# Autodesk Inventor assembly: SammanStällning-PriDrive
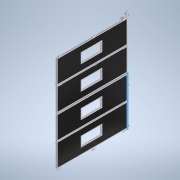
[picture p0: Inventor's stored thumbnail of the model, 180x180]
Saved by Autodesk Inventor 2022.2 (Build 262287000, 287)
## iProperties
Created: 2022-02
Part Number: SammanStällning-PriDrive
Document SubType Name: Assembly
Designer: cl
Author: cl
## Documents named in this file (17)
- G:\AutoCad\Carl Lund\3D-modeller systemlösningar\3D-modell-systemlösning-2022\SammanStällning-PriDrive.iam
- G:\AutoCad\Carl Lund\3D-modeller systemlösningar\3D-modell-systemlösning-2022\Parts\BladKomplett2022.iam
- G:\AutoCad\Carl Lund\3D-modeller systemlösningar\3D-modell-systemlösning-2022\Parts\MellanGångjärnH.ipt
- G:\AutoCad\Carl Lund\3D-modeller systemlösningar\3D-modell-systemlösning-2022\Parts\MellanGångjärnV.ipt
- G:\AutoCad\Carl Lund\3D-modeller systemlösningar\3D-modell-systemlösning-2022\Parts\Karmstyrning.ipt
- G:\AutoCad\Carl Lund\3D-modeller systemlösningar\3D-modell-systemlösning-2022\Parts\SidotätningUppe.ipt
- G:\AutoCad\Carl Lund\3D-modeller systemlösningar\3D-modell-systemlösning-2022\Parts\SidoTätning.ipt
- G:\AutoCad\Carl Lund\3D-modeller systemlösningar\3D-modell-systemlösning-2022\Parts\SläpList.ipt
- G:\AutoCad\Carl Lund\3D-modeller systemlösningar\3D-modell-systemlösning-2022\Parts\GummilistMellan.ipt
- G:\AutoCad\Carl Lund\3D-modeller systemlösningar\3D-modell-systemlösning-2022\Styrande.iam
- G:\AutoCad\Carl Lund\3D-modeller systemlösningar\3D-modell-systemlösning-2022\Parts\GarageregelHöger.ipt
- G:\AutoCad\Carl Lund\3D-modeller systemlösningar\3D-modell-systemlösning-2022\Parts\GarageregelVänster.ipt
- G:\AutoCad\Carl Lund\3D-modeller systemlösningar\3D-modell-systemlösning-2022\Parts\styrrulle.ipt
- G:\AutoCad\Carl Lund\3D-modeller systemlösningar\3D-modell-systemlösning-2022\Parts\Styrskena.ipt
- G:\AutoCad\Carl Lund\3D-modeller systemlösningar\3D-modell-systemlösning-2022\Parts\PriDrive\Karmgångjärn-PriDrive.ipt
- G:\AutoCad\Carl Lund\3D-modeller systemlösningar\3D-modell-systemlösning-2022\Parts\PriDrive\VinkeljärnStyrskena2.ipt
- G:\AutoCad\Carl Lund\3D-modeller systemlösningar\3D-modell-systemlösning-2022\Parts\PriDrive\VinkeljärnStyrskena.ipt
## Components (43 placed, 15 different names)
1. Karmgångjärn-PriDrive:1 — Mate:177, Flush:176, Mate:178, Flush:177, Flush:179, Flush:180
2. VinkeljärnStyrskena2:1 — Flush:179, Flush:180, Mate:181
3. VinkeljärnStyrskena2:2 — Flush:177, Flush:178, Mate:180, Flush:181, Flush:182
4. VinkeljärnStyrskena:1 — Mate:182, Flush:181, Flush:182
5. BladKomplett2022:1 [sub-assembly] — Mate:1, Mate:2, Flush:1, Flush:2, Flush:3, Flush:8, Flush:28, Flush:29, Mate:28, Flush:30, Mate:42, Mate:39, Mate:43, Flush:99, Flush:100, Flush:101, Flush:102, Flush:103, Flush:104, Flush:112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
6. BladKomplett2022:2 [sub-assembly] — Flush:2, Flush:3, Flush:8, Flush:106, Mate:52, Flush:107, Flush:118, Flush:121, Mate:65, Flush:148, Flush:149, Mate:82, Flush:170, Flush:171
7. BladKomplett2022:3 [sub-assembly] — Flush:30, Flush:101, Flush:102, Mate:53, Flush:114, Flush:115
8. BladKomplett2022:4 [sub-assembly] — Flush:32, Flush:100, Flush:103, Mate:54, Flush:122, Flush:123, Flush:128, Mate:64, Flush:146, Flush:147, Flush:178
9. BladKomplett2022:5 [sub-assembly] — Flush:31, Flush:99, Flush:104, Flush:129, Mate:55, Flush:130, Mate:63, Flush:144, Flush:145, Mate:81, Flush:168, Flush:169
10. BladKomplett2022:6 [sub-assembly] — Mate:28, Flush:28, Flush:29, Flush:31, Flush:32, Mate:38, Flush:131, Flush:134, Flush:137, Mate:56, Flush:138, Flush:139, Mate:58, Mate:59, Mate:62, Flush:142, Flush:143, Flush:152, Mate:69, Mate:70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
11. GarageregelHöger:1 — Flush:156, Flush:157, Flush:158
12. GarageregelHöger:2 — Mate:77, Flush:154, Flush:155, Flush:156, Flush:157, Flush:158
13. GarageregelVänster:1 — Flush:161, Flush:162, Flush:163
14. GarageregelVänster:2 — Mate:78, Flush:159, Flush:160, Flush:161, Flush:162, Flush:163
15. Karmstyrning:2 — Mate:38, Mate:56, Flush:138, Flush:141
16. Karmstyrning:3 — Mate:39, Mate:43, Flush:140
17. Karmstyrning:4 — Mate:42, Mate:60, Mate:61, Flush:141
18. Karmstyrning:1 — Flush:139, Mate:58, Mate:59, Flush:140
19. MellanGångjärnV:3 — Flush:110, Flush:111, Flush:113
20. MellanGångjärnV:2 — Flush:108, Flush:109, Flush:110, Flush:111, Flush:112
21. MellanGångjärnV:1 — Flush:106, Mate:52, Flush:107, Flush:108, Flush:109
22. MellanGångjärnH:2 — Flush:116, Flush:117, Flush:118, Flush:119, Flush:120
23. MellanGångjärnH:3 — Flush:119, Flush:120, Flush:121
24. MellanGångjärnH:1 — Mate:53, Flush:114, Flush:115, Flush:116, Flush:117
25. MellanGångjärnV:6 — Flush:124, Flush:125, Flush:126, Flush:127, Flush:128
26. MellanGångjärnV:5 — Flush:126, Flush:127, Flush:129
27. MellanGångjärnV:4 — Mate:54, Flush:122, Flush:123, Flush:124, Flush:125
28. MellanGångjärnH:5 — Flush:132, Flush:133, Flush:134
29. MellanGångjärnH:6 — Flush:135, Flush:136, Flush:137
30. MellanGångjärnH:4 — Mate:55, Flush:130, Flush:131, Flush:132, Flush:133, Flush:135, Flush:136
31. GummilistMellan:2 — Mate:63, Flush:144, Flush:145
32. GummilistMellan:3 — Mate:64, Flush:146, Flush:147
33. GummilistMellan:4 — Mate:65, Flush:148, Flush:149
34. GummilistMellan:5 — Mate:66, Flush:150, Flush:151
35. SidotätningUppe:1 — Mate:67, Mate:68, Flush:152, Mate:71, Mate:74
36. SidoTätning:1 — Mate:69, Mate:70, Mate:71, Mate:76
37. SidoTätning:2 — Mate:72, Mate:73, Mate:74
38. SläpList:1 — Mate:75, Flush:153, Mate:76
39. GummilistMellan:1 — Mate:62, Flush:142, Flush:143
40. styrrulle:1 — Mate:81, Flush:168, Flush:169
41. styrrulle:2 — Mate:82, Flush:170, Flush:171, Tangent:1
42. Styrskena:1 — Tangent:1, Flush:174, Flush:175, Mate:181
43. Styrskena:2 — Flush:174, Flush:175, Mate:179, Mate:180, Mate:182
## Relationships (128: Flush 86, Mate 41, Tangent 1)
- Mate:1: BladKomplett2022:1
- Mate:2: BladKomplett2022:1
- Flush:1: BladKomplett2022:1
- Flush:2: BladKomplett2022:1 ↔ BladKomplett2022:2
- Flush:3: BladKomplett2022:1 ↔ BladKomplett2022:2
- Flush:8: BladKomplett2022:1 ↔ BladKomplett2022:2
- Mate:28: BladKomplett2022:1 ↔ BladKomplett2022:6
- Flush:28: BladKomplett2022:1 ↔ BladKomplett2022:6
- Flush:29: BladKomplett2022:1 ↔ BladKomplett2022:6
- Flush:30: BladKomplett2022:1 ↔ BladKomplett2022:3
- Flush:31: BladKomplett2022:5 ↔ BladKomplett2022:6
- Flush:32: BladKomplett2022:4 ↔ BladKomplett2022:6
- Mate:38: BladKomplett2022:6 ↔ Karmstyrning:2
- Mate:39: BladKomplett2022:1 ↔ Karmstyrning:3
- Mate:42: BladKomplett2022:1 ↔ Karmstyrning:4
- Mate:43: BladKomplett2022:1 ↔ Karmstyrning:3
- Flush:99: BladKomplett2022:1 ↔ BladKomplett2022:5
- Flush:100: BladKomplett2022:1 ↔ BladKomplett2022:4
- Flush:101: BladKomplett2022:1 ↔ BladKomplett2022:3
- Flush:102: BladKomplett2022:1 ↔ BladKomplett2022:3
- Flush:103: BladKomplett2022:1 ↔ BladKomplett2022:4
- Flush:104: BladKomplett2022:1 ↔ BladKomplett2022:5
- Flush:106: BladKomplett2022:2 ↔ MellanGångjärnV:1
- Mate:52: BladKomplett2022:2 ↔ MellanGångjärnV:1
- Flush:107: BladKomplett2022:2 ↔ MellanGångjärnV:1
- Flush:108: MellanGångjärnV:2 ↔ MellanGångjärnV:1
- Flush:109: MellanGångjärnV:2 ↔ MellanGångjärnV:1
- Flush:110: MellanGångjärnV:3 ↔ MellanGångjärnV:2
- Flush:111: MellanGångjärnV:3 ↔ MellanGångjärnV:2
- Flush:112: BladKomplett2022:1 ↔ MellanGångjärnV:2
- Flush:113: BladKomplett2022:1 ↔ MellanGångjärnV:3
- Mate:53: BladKomplett2022:3 ↔ MellanGångjärnH:1
- Flush:114: BladKomplett2022:3 ↔ MellanGångjärnH:1
- Flush:115: BladKomplett2022:3 ↔ MellanGångjärnH:1
- Flush:116: MellanGångjärnH:2 ↔ MellanGångjärnH:1
- Flush:117: MellanGångjärnH:2 ↔ MellanGångjärnH:1
- Flush:118: BladKomplett2022:2 ↔ MellanGångjärnH:2
- Flush:119: MellanGångjärnH:2 ↔ MellanGångjärnH:3
- Flush:120: MellanGångjärnH:2 ↔ MellanGångjärnH:3
- Flush:121: BladKomplett2022:2 ↔ MellanGångjärnH:3
- Mate:54: BladKomplett2022:4 ↔ MellanGångjärnV:4
- Flush:122: BladKomplett2022:4 ↔ MellanGångjärnV:4
- Flush:123: BladKomplett2022:4 ↔ MellanGångjärnV:4
- Flush:124: MellanGångjärnV:6 ↔ MellanGångjärnV:4
- Flush:125: MellanGångjärnV:6 ↔ MellanGångjärnV:4
- Flush:126: MellanGångjärnV:6 ↔ MellanGångjärnV:5
- Flush:127: MellanGångjärnV:6 ↔ MellanGångjärnV:5
- Flush:128: BladKomplett2022:4 ↔ MellanGångjärnV:6
- Flush:129: BladKomplett2022:5 ↔ MellanGångjärnV:5
- Mate:55: BladKomplett2022:5 ↔ MellanGångjärnH:4
- Flush:130: BladKomplett2022:5 ↔ MellanGångjärnH:4
- Flush:131: BladKomplett2022:6 ↔ MellanGångjärnH:4
- Flush:132: MellanGångjärnH:5 ↔ MellanGångjärnH:4
- Flush:133: MellanGångjärnH:5 ↔ MellanGångjärnH:4
- Flush:134: BladKomplett2022:6 ↔ MellanGångjärnH:5
- Flush:135: MellanGångjärnH:6 ↔ MellanGångjärnH:4
- Flush:136: MellanGångjärnH:6 ↔ MellanGångjärnH:4
- Flush:137: BladKomplett2022:6 ↔ MellanGångjärnH:6
- Mate:56: BladKomplett2022:6 ↔ Karmstyrning:2
- Flush:138: BladKomplett2022:6 ↔ Karmstyrning:2
- Flush:139: BladKomplett2022:6 ↔ Karmstyrning:1
- Mate:58: BladKomplett2022:6 ↔ Karmstyrning:1
- Mate:59: BladKomplett2022:6 ↔ Karmstyrning:1
- Flush:140: Karmstyrning:3 ↔ Karmstyrning:1
- Mate:60: BladKomplett2022:1 ↔ Karmstyrning:4
- Mate:61: BladKomplett2022:1 ↔ Karmstyrning:4
- Flush:141: Karmstyrning:2 ↔ Karmstyrning:4
- Mate:62: BladKomplett2022:6 ↔ GummilistMellan:1
- Flush:142: BladKomplett2022:6 ↔ GummilistMellan:1
- Flush:143: BladKomplett2022:6 ↔ GummilistMellan:1
- Mate:63: BladKomplett2022:5 ↔ GummilistMellan:2
- Flush:144: BladKomplett2022:5 ↔ GummilistMellan:2
- Flush:145: BladKomplett2022:5 ↔ GummilistMellan:2
- Mate:64: BladKomplett2022:4 ↔ GummilistMellan:3
- Flush:146: BladKomplett2022:4 ↔ GummilistMellan:3
- Flush:147: BladKomplett2022:4 ↔ GummilistMellan:3
- Mate:65: BladKomplett2022:2 ↔ GummilistMellan:4
- Flush:148: BladKomplett2022:2 ↔ GummilistMellan:4
- Flush:149: BladKomplett2022:2 ↔ GummilistMellan:4
- Mate:66: BladKomplett2022:1 ↔ GummilistMellan:5
- Flush:150: BladKomplett2022:1 ↔ GummilistMellan:5
- Flush:151: BladKomplett2022:1 ↔ GummilistMellan:5
- Mate:67: BladKomplett2022:1 ↔ SidotätningUppe:1
- Mate:68: BladKomplett2022:1 ↔ SidotätningUppe:1
- Flush:152: BladKomplett2022:6 ↔ SidotätningUppe:1
- Mate:69: BladKomplett2022:6 ↔ SidoTätning:1
- Mate:70: BladKomplett2022:6 ↔ SidoTätning:1
- Mate:71: SidotätningUppe:1 ↔ SidoTätning:1
- Mate:72: BladKomplett2022:1 ↔ SidoTätning:2
- Mate:73: BladKomplett2022:1 ↔ SidoTätning:2
- Mate:74: SidotätningUppe:1 ↔ SidoTätning:2
- Mate:75: BladKomplett2022:1 ↔ SläpList:1
- Flush:153: BladKomplett2022:1 ↔ SläpList:1
- Mate:76: SidoTätning:1 ↔ SläpList:1
- Mate:77: BladKomplett2022:1 ↔ GarageregelHöger:2
- Flush:154: BladKomplett2022:1 ↔ GarageregelHöger:2
- Flush:155: BladKomplett2022:1 ↔ GarageregelHöger:2
- Flush:156: GarageregelHöger:1 ↔ GarageregelHöger:2
- Flush:157: GarageregelHöger:1 ↔ GarageregelHöger:2
- Flush:158: GarageregelHöger:1 ↔ GarageregelHöger:2
- Mate:78: BladKomplett2022:6 ↔ GarageregelVänster:2
- Flush:159: BladKomplett2022:6 ↔ GarageregelVänster:2
- Flush:160: BladKomplett2022:6 ↔ GarageregelVänster:2
- Flush:161: GarageregelVänster:1 ↔ GarageregelVänster:2
- Flush:162: GarageregelVänster:1 ↔ GarageregelVänster:2
- Flush:163: GarageregelVänster:1 ↔ GarageregelVänster:2
- Mate:81: BladKomplett2022:5 ↔ styrrulle:1
- Flush:168: BladKomplett2022:5 ↔ styrrulle:1
- Flush:169: BladKomplett2022:5 ↔ styrrulle:1
- Mate:82: BladKomplett2022:2 ↔ styrrulle:2
- Flush:170: BladKomplett2022:2 ↔ styrrulle:2
- Flush:171: BladKomplett2022:2 ↔ styrrulle:2
- Tangent:1: styrrulle:2 ↔ Styrskena:1
- Flush:174: Styrskena:1 ↔ Styrskena:2
- Flush:175: Styrskena:1 ↔ Styrskena:2
- Mate:177: Karmgångjärn-PriDrive:1 ↔ BladKomplett2022:1
- Flush:176: Karmgångjärn-PriDrive:1 ↔ BladKomplett2022:1
- Mate:178: Karmgångjärn-PriDrive:1 ↔ BladKomplett2022:1
- Flush:177: Karmgångjärn-PriDrive:1 ↔ VinkeljärnStyrskena2:2
- Flush:178: VinkeljärnStyrskena2:2 ↔ BladKomplett2022:4
- Mate:179: BladKomplett2022:6 ↔ Styrskena:2
- Mate:180: VinkeljärnStyrskena2:2 ↔ Styrskena:2
- Flush:179: Karmgångjärn-PriDrive:1 ↔ VinkeljärnStyrskena2:1
- Flush:180: Karmgångjärn-PriDrive:1 ↔ VinkeljärnStyrskena2:1
- Mate:181: VinkeljärnStyrskena2:1 ↔ Styrskena:1
- Mate:182: VinkeljärnStyrskena:1 ↔ Styrskena:2
- Flush:181: VinkeljärnStyrskena2:2 ↔ VinkeljärnStyrskena:1
- Flush:182: VinkeljärnStyrskena2:2 ↔ VinkeljärnStyrskena:1
## Named parameters: Blad2 = 1012.5 mm, Blad3 = 0, Blad4 = 0, Blad5 = 1012.5 mm, MGJ12Djup = 0, MGJ12Bredd = 0, MGJ56Djup = 0, MGJ56Bredd = 0, MGJ23Djup = 48 mm, MGJ45Djup = 48 mm, GarageRegel5 = 0, GarageRegel6 = 0, BladBredd = 987.5 mm, Fönsterhöjd = 862 mm, Blad2_1 = 1012.5 mm, Blad3_1 = 0, Blad4_1 = 0, Blad5_1 = 1012.5 mm, Blad6 = 2025 mm, MGJ12Djup_1 = 0, MGJ12Bredd_1 = 0, MGJ2Djup = 0, MGJ2Bredd = 5012.5 mm, MGJ56Djup_1 = 0, MGJ56Bredd_1 = 0, MGJ23Djup_1 = 48 mm, MGJ45Djup_1 = 48 mm, GarageRegel5_1 = 0, GarageRegel6_1 = 0, Styrrulle2Djup = 0, FönsterhöjdStyrning = 862 mm, FönsterKarm = 54 mm, AndraGlasraden = 0, BrösthöjdStyrning2 = 0.0001 mm, InfälldGångDörr = 0, Infälldstyr = 1012.5 mm, EnDelGångDörr = 0, VinkelJärnStyrSkena = 1456.25 mm
